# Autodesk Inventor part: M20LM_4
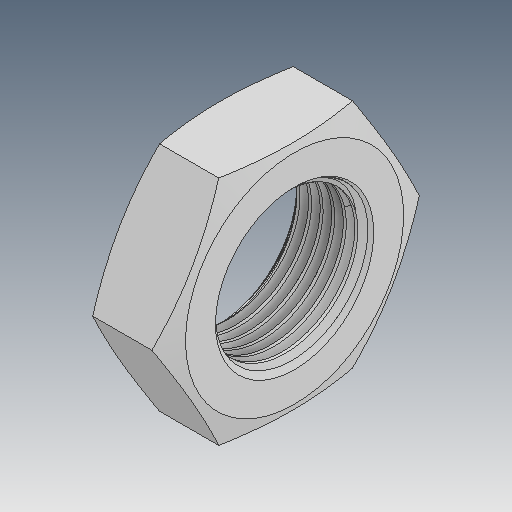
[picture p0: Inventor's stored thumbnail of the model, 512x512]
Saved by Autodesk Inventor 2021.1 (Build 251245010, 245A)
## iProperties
Created: 2019-04
Part Number: M20LM_4
Material: Ogólny
Document SubType Name: Modeling
Designer: user
Density: 1 g/cm^3
Appearance: Domyślna
Author: user
Revision Number: ÈÎºÎ
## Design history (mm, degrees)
feature "ÊäÈë1"
node "Bryła1"
